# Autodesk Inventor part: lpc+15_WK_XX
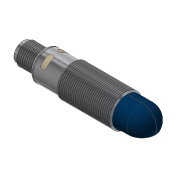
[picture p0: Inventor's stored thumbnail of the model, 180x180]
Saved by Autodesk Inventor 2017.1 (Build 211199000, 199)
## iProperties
Shininess: 20.0
Length Units: 11269
Angle Units: 11279
Time Units: 11290
Mass Units: 11283
Length Display Precision: 2
Angle Display Precision: 2
Part Number: lpc+15_WK_XX
Material: Nichtrostender Stahl - 440C
Document SubType Name: Modellieren
Description: Ipc-25 /CXX/M18
Checked By: Alves
Created: 2005-08
Designer: Ohle
Manufacturer: Standard
Standards Organization: Custom
Appearance: Aluminium - poliert
Density: 0.0
Volumn: 0.0
Area: 0.0
PropertySet Name: Model Information
Control State: 0
Master: False
Checked Out: False
BESTELLNUMMER: Ipc-25 /CXX/M18
ME: ST
Title: Ipc Sensoren
Author: Ohle
Comments: keine Bemerkung
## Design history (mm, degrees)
sketch "Skizze10"
  geometry: L1 (-43.018, 0)-(22.982, 0); L2 (-39.018, 6.5)-(-39.018, 7.25); L3 (-45.9, 8)-(-45.9, 8); L4 (-23.268, 9)-(5.732, 9); L5 (1.482, 0)-(-82.2, 0); L6 (-24.018, 8.25)-(-23.268, 9); L7 (6.482, 8.25)-(5.732, 9); L8 (-50.518, 6)-(-39.518, 6); L9 (-37.418, 8.25)-(-24.018, 8.25); L10 (-51.018, 4.5)-(-43.018, 4.5); L11 (-43.018, 0)-(-43.018, 4.5); L12 (-37.518, 8.25)-(-38.018, 8.25); L13 (-39.518, 6)-(-39.018, 6.5); L14 (-51.018, 5.5)-(-51.018, 4.5); L15 (-51.018, 5.5)-(-50.518, 6); L16 (-37.518, 8.25)-(-37.518, 8.15); L17 (-37.518, 8.15)-(-37.418, 8.15); L18 (-37.418, 8.15)-(-37.418, 8.25); L19 (6.482, 8.25)-(14.732, 8.25); L20 (22.982, 0)-(22.982, 0); A1 r 1 centre (-38.018, 7.25) between (-38.018, 8.25) and (-39.018, 7.25); A2 r 8.25 centre (14.732, 0) between (22.982, 0) and (14.732, 8.25); 4 further points
  constraints: 41 end point, 8 point on line, 5 parallel, 4 perpendicular, 4 point on circle, 4 tangent, 2 centre point, 2 horizontal, 1 collinear
  dimensions: "d171" = 4.5 distance between parallel lines of L10 L1; "d250" = 0.75 distance from line of L7.start L4; "d256" = 45 deg angle of L4 L6; "d257" = 8.25 distance between parallel lines of L5 L9; "d263" = 8.25 distance between parallel lines of L5 L12; "d266" = 12 distance from line of L2 L14.start; "d269" = 6 distance between parallel lines of L5 L8; "d289" = 135 deg angle of L7 L4; "d290" = 0.5 horizontal distance of L8.end L2.start; "d291" = 45 deg angle of L13 L8 (derived); "d293" = 0.5 horizontal distance of L14.start L8.start; "d294" = 45 deg angle of L15 L8 (derived); "d295" = 8 distance of L10.start L10.end; "d296" = 1.5 distance of L12.start point (-39.018, 8.25); "d297" = 0.1 distance of L16.end L17.end; "d298" = 8.15 distance between parallel lines of L17 L1; "d299" = 15 distance from line of L6.start L2; "d300" = 1 radius of A1; "d338" = 8.25 radius of A2; "d339" = 16.5 horizontal distance of L20.end L7.start; "d340" = 8.25 distance between parallel lines of L1 L19 (derived); "d365" = 30.5 distance of L7.start L6.start
revolve "Grundkörper pico+" sketch "Skizze10" stored, may be unused: angle "d168" = 90 deg
feature "Gewinde M12" dims "d174" = 10, "d175" = 0
feature "Gewinde M 18" dims "d179" = 10, "d180" = 0
workplane "Arbeitsebene1"
workplane "Arbeitsebene2"
sketch "Skizze13"
  geometry: L1 (-3.409, -3.409)-(3.61, 3.61); L2 (-3.439, 3.439)-(4.105, -4.105); L3 (-12.6, 0)-(12.6, 0) reference; C1 r 0.5 at (2.121, -2.121); C2 r 0.5 at (2.121, 2.121); C3 r 0.5 at (-2.121, 2.121); C4 r 0.5 at (-2.121, -2.121); C5 r 4.5 at (0, 0) reference; C6 r 0.5 at (0, 0); A1 r 3 centre (0, 0) between (-2.121, 2.121) and (2.121, 2.121); 2 further points
  constraints: 6 centre point, 6 point on line, 4 coincident, 4 end point, 4 equal radius, 4 point on circle, 1 horizontal alignment, 1 perpendicular
  dimensions: "d208" = 1 diameter of C3; "d209" = 6 diameter of A1
extrude "Pole" join sketch "Skizze13" distance "d212" = 7; taper "d213" = 0 deg
fillet "Rundung Pole" dims "d214" = 0.5
sketch "Skizze14"
  geometry: C1 r 0.5 at (0, -4.5); A1 r 4.5 centre (0, 0) between (4.435, -0.762) and (4.435, 0.762); A2 r 4.5 centre (0, 0) between (0, 4.5) and (0.499, 4.472) reference; A3 r 0.5 centre (0, 4.5) between (-0.499, 4.472) and (0.499, 4.472); 3 further points
  constraints: 9 point on circle, 3 centre point, 3 coincident, 1 horizontal alignment, 1 vertical alignment
  dimensions: "d215" = 9 diameter of A1; "d280" = 1 diameter of A3; "d330" = 1 diameter of C1
extrude "Verdrehsicherung" join sketch "Skizze14" distance "d217" = 7; taper "d218" = 0 deg
sketch "Skizze18"
  geometry: C1 r 7.25 at (0, 0) reference; C2 r 1 at (-8.15, 0)
  constraints: 1 centre point, 1 horizontal alignment
  dimensions: "d328" = 2 diameter of C2; "d329" = 8.15 distance of C1.centre C2.centre
extrude "Bohrung Ausrichtung" cut sketch "Skizze18" distance "d316" = 0.75; taper "d317" = 0 deg
workplane "Arbeitsebene4"
sketch "Skizze19"
  geometry: L1 (-39.018, 0)-(-30.18, 0); L2 (-34.718, -7.5)-(-34.718, -3); L3 (-31.718, -7.5)-(-31.718, -3); L4 (-31.718, 3)-(-31.718, 7.5); L5 (-34.718, 3)-(-34.718, 7.5); A1 r 1.5 centre (-33.218, 3) between (-31.718, 3) and (-34.718, 3); A2 r 1.5 centre (-33.218, -3) between (-34.718, -3) and (-31.718, -3); A3 r 1.5 centre (-33.218, 7.5) between (-31.718, 7.5) and (-34.718, 7.5); A4 r 1.5 centre (-33.218, -7.5) between (-34.718, -7.5) and (-31.718, -7.5); 4 further points; 1 other entity
  constraints: 10 end point, 8 point on circle, 8 tangent, 4 centre point, 3 equal radius, 2 vertical alignment, 1 horizontal, 2 other
  dimensions: "d319" = 3 diameter of A2; "d320" = 6 distance of A2.centre A1.centre; "d321" = 4.5 distance of A1.centre A3.centre; "d322" = 4.5 distance of A4.centre A2.centre; "d323" = 3 distance from line of A2.centre L1; "d324" = 5.8 dimension on A1.centre; "d325" = 5.8 dimension on A2.centre
feature "Prägen LED-Fenster" sketch "Skizze19" dims "d326" = 0.01, "d327" = 0
workplane "Arbeitsebene5"
sketch "Skizze20"
  geometry: L1 (14.732, -8.25)-(14.732, 8.25) reference; L2 (6.482, -8.25)-(6.482, 8.25) reference; L3 (14.732, -8.25)-(14.732, 8.25) reference; L4 (6.982, -8.25)-(24.008, -8.25); L5 (24.008, -8.25)-(24.008, 8.25); L6 (24.008, 8.25)-(6.982, 8.25); L7 (6.982, 8.25)-(6.982, -8.25)
  constraints: 8 end point, 2 parallel, 1 horizontal, 1 perpendicular
  dimensions: "d342" = 0.5 distance between parallel lines of L7 L2
extrude "USW-Fläche Winkelkopf" cut sketch "Skizze20" distance "d343" = 4.8; taper "d344" = 0 deg
sketch "Skizze21"
  geometry: C1 r 7 at (-14.732, 0); A1 r 7.494 centre (-14.732, 0) between (-14.732, 7.494) and (-14.732, -7.494) reference
  constraints: 1 centre point, 1 coincident
  dimensions: "d345" = 14 diameter of C1
extrude "Extrusion6" cut sketch "Skizze21" distance "d346" = 0.01; taper "d347" = 0 deg
sketch "Skizze22"
  geometry: C1 r 7 at (0, 0) reference; C2 r 2.5 at (0, 0)
  constraints: 1 centre point, 1 coincident
  dimensions: "d348" = 5 diameter of C2
extrude "Extrusion7" join sketch "Skizze22" distance "d349" = 0.01; taper "d350" = 0 deg
sketch "Skizze28"
  geometry: L1 (-6.482, 8.25)-(-14.732, 8.25) reference; L2 (-6.482, 8.25)-(-6.482, -8.25) reference; L3 (-14.732, -3.45)-(-22.226, -3.45) reference; L4 (-14.732, 8.15)-(-6.482, 8.15); A1 r 8.25 centre (-14.732, 0) between (-14.732, 8.25) and (-22.226, -3.45) reference; A2 r 8.15 centre (-14.732, 0) between (-14.732, 8.15) and (-22.116, -3.45)
  constraints: 2 end point, 2 point on circle, 2 point on line, 1 centre point, 1 coincident, 1 perpendicular, 1 tangent
  dimensions: "d362" = 0.1 radial gap between concentric circles of A2 A1
extrude "Extrusion8" cut sketch "Skizze28" stored distance "d363" = 0.3; taper "d364" = 0 deg
sketch "Skizze29"
  geometry: C1 r 5.5 at (0, 0); C2 r 4.5 at (0, 0); C3 r 4.15 at (0, 0); C4 r 5.25 at (0, 0); 2 further points
  constraints: 4 centre point
  dimensions: "d366" = 8.3 diameter of C3; "d367" = 10.5 diameter of C4
extrude "Extrusion9" join sketch "Skizze29" distance "d368" = 0.2; taper "d369" = 0 deg
sketch "Skizze30"
  geometry: C1 r 5.25 at (0, 0) reference; C2 r 8.312 at (0, 0); 1 further point
  constraints: 1 centre point
extrude "Extrusion10" cut sketch "Skizze30" distance "d370" = 1.8; taper "d371" = 0 deg
chamfer "Fase2" distance "d372" = 0.75; stored, may be unused: second distance "d373" = 2, angle "d374" = 30 deg
node "Volumenkörper1"
node "Volumenkörper"
node "Flächenkörper"
node "Projizierte Kontur2"
node "Projizierte Kontur3"
other parameters: "d10" = 14, "d73" = -35, "d130" = 0.2, "d207" = -95.5, "d318" = 8.25, "d341" = -8.25
